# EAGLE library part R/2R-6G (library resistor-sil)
R/2R Ladder 6 Murata RGSD12L
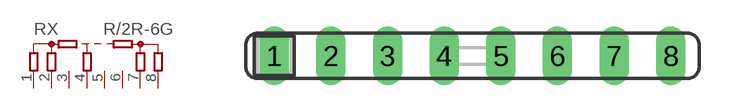
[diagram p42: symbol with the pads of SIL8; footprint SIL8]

Designator prefix RX

## R/2R-6G (OC_FARNELL: unknown; OC_NEWARK: unknown)  [SIL8]
1  IN  pas
2  B6  pas
3  B5  pas
4  B4  pas
5  B3  pas
6  B2  pas
7  B1  pas
8  OUT  pas

## Footprint SIL8 (pad centres in mm)
Single In Line
drill 0.813 long: 1 -8.89,0; 2 -6.35,0; 3 -3.81,0; 4 -1.27,0; 5 1.27,0; 6 3.81,0; 7 6.35,0; 8 8.89,0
